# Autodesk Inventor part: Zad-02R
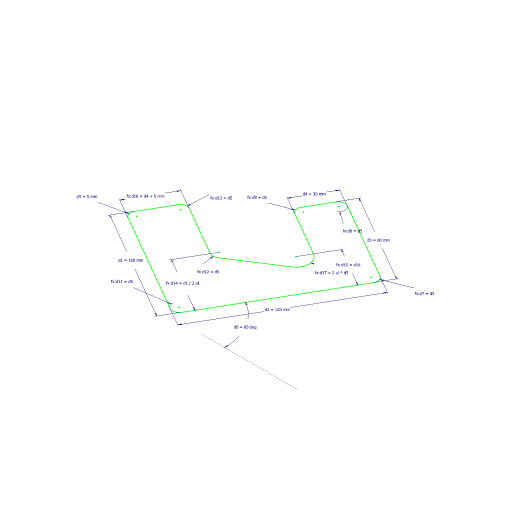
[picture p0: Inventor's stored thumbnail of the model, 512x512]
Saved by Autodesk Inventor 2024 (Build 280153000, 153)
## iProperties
Company: ATC
Shininess: 20.0
Length Units: 11269
Angle Units: 11279
Time Units: 11290
Mass Units: 11283
Created: 2023-03
Part Number: Zad-02R
Document SubType Name: Modeling
Designer: Andrzej Jaskulski
Density: 1 g/cm^3
Material: Kurs-AJ
Appearance: Kurs-AJ
Checked By: A.J.
Engr Approved By: Andrzej Jaskulski
Mfg Approved By: Andrzej Jaskulski
Authority: A.J.
Density: 0.0
Volumn: 0.0
Area: 0.0
PropertySet Name: Model Information
Control State: 0
Master: False
Checked Out: False
Title: A.J.: Kurs R2024-MEP
Author: Andrzej Jaskulski
Revision Number: 1/24
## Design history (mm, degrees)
sketch "Zad 02R"
  geometry: L1 (-2.518, -11.615)-(71.903, -11.615) reference; L2 (-25.519, -4.716)-(29.481, 90.547); L3 (27.651, 97.377)-(-32.971, 132.377); L4 (-39.801, 130.547)-(-49.801, 113.226); L5 (-47.971, 106.396)-(-13.33, 86.396); L6 (-12.924, 69.323)-(-48.617, 46.388); L7 (-53.82, 46.265)-(-92.791, 68.765); L8 (-99.621, 66.935)-(-112.121, 45.284); L9 (-110.291, 38.454)-(-32.349, -6.546); A1 r 5 centre (-45.471, 110.726) between (-49.801, 113.226) and (-47.971, 106.396); A2 r 10 centre (-18.33, 77.736) between (-12.924, 69.323) and (-13.33, 86.396); A3 r 5 centre (-95.291, 64.435) between (-92.791, 68.765) and (-99.621, 66.935); A4 r 5 centre (-107.791, 42.784) between (-112.121, 45.284) and (-110.291, 38.454); A5 r 5 centre (-51.32, 50.595) between (-53.82, 46.265) and (-48.617, 46.388); A6 r 5 centre (-35.471, 128.047) between (-32.971, 132.377) and (-39.801, 130.547); A7 r 5 centre (25.151, 93.047) between (29.481, 90.547) and (27.651, 97.377); A8 r 5 centre (-29.849, -2.216) between (-32.349, -6.546) and (-25.519, -4.716)
  constraints: 18 end point, 16 point on circle, 16 tangent, 8 centre point, 5 parallel, 2 horizontal, 1 perpendicular
  dimensions: "d6" = 60 deg angle of L2 L1; "d7" = 5 radius of A7 (= d5); "d8" = 5 radius of A6 (= d5); "d9" = 5 radius of A1 (= d5); "d17" = 10 radius of A2 (= 2 x d5); "d12" = 5 radius of A5 (= d5); "d13" = 5 radius of A3 (= d5); "d5" = 5 radius of A4; "d11" = 5 radius of A8 (= d5); "d1" = 100 distance between parallel lines of L2 L8; "d2" = 120 distance between parallel lines of L3 L9; "d3" = 80 distance between parallel lines of L2 L4; "d4" = 30 distance between parallel lines of L5 L3; "d16" = 35 distance between parallel lines of L9 L7 (computed from d4); "d14" = 50 distance from line of A5.centre L2 (= 0.5 x d1); "d15" = 35 distance from line of L2 A2.centre (= d16)
node "Korpusy bryłowe"
node "Korpusy powierzchniowe"
